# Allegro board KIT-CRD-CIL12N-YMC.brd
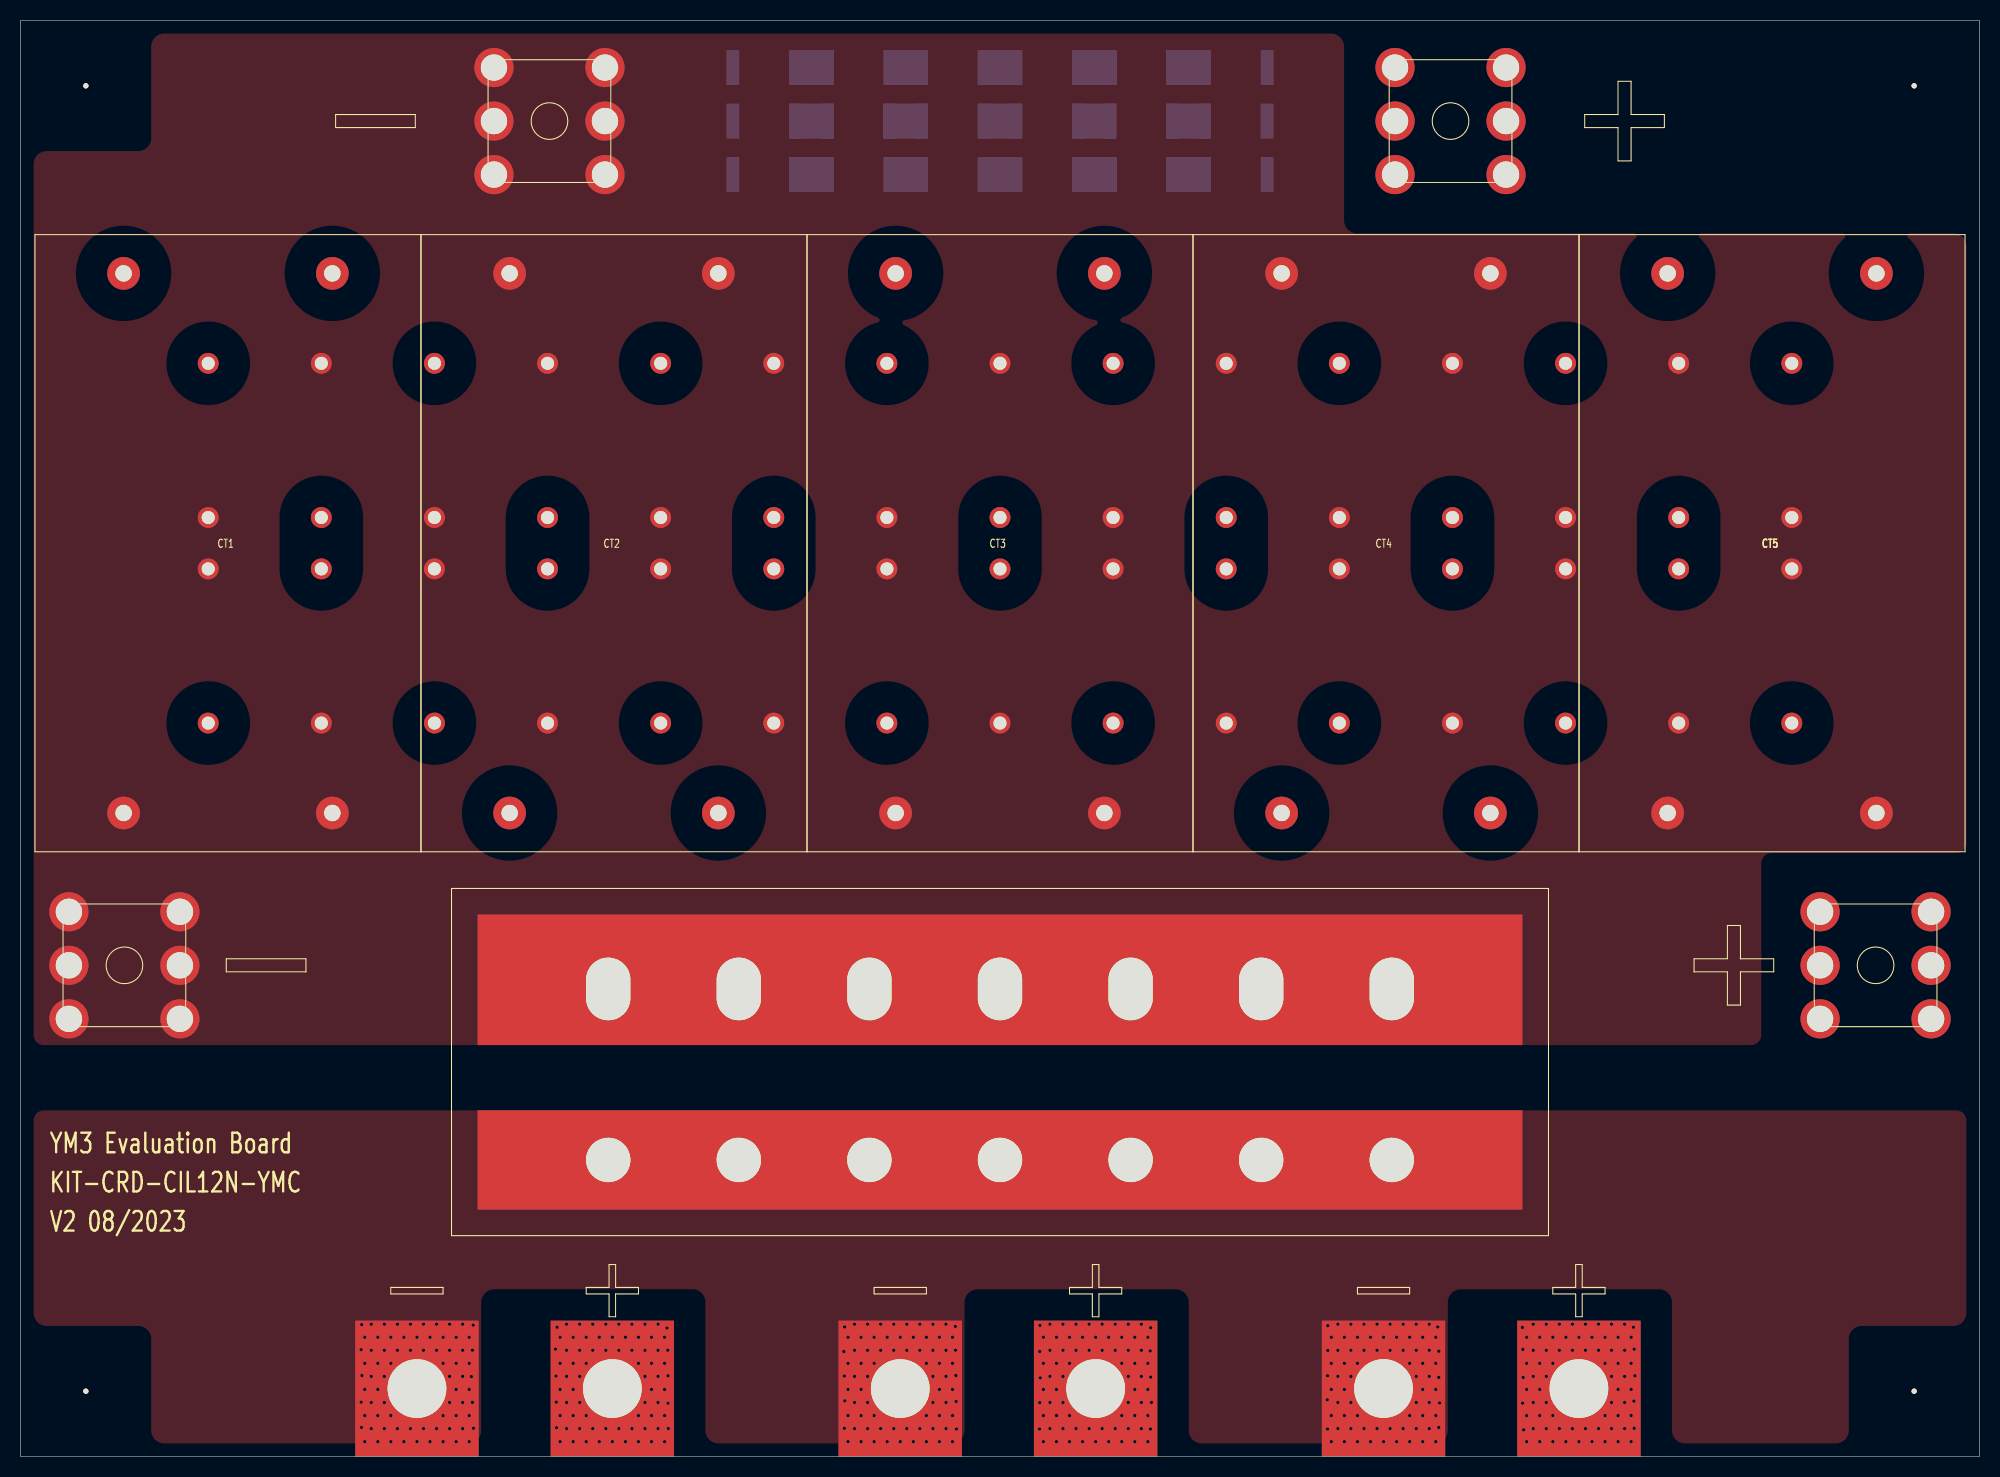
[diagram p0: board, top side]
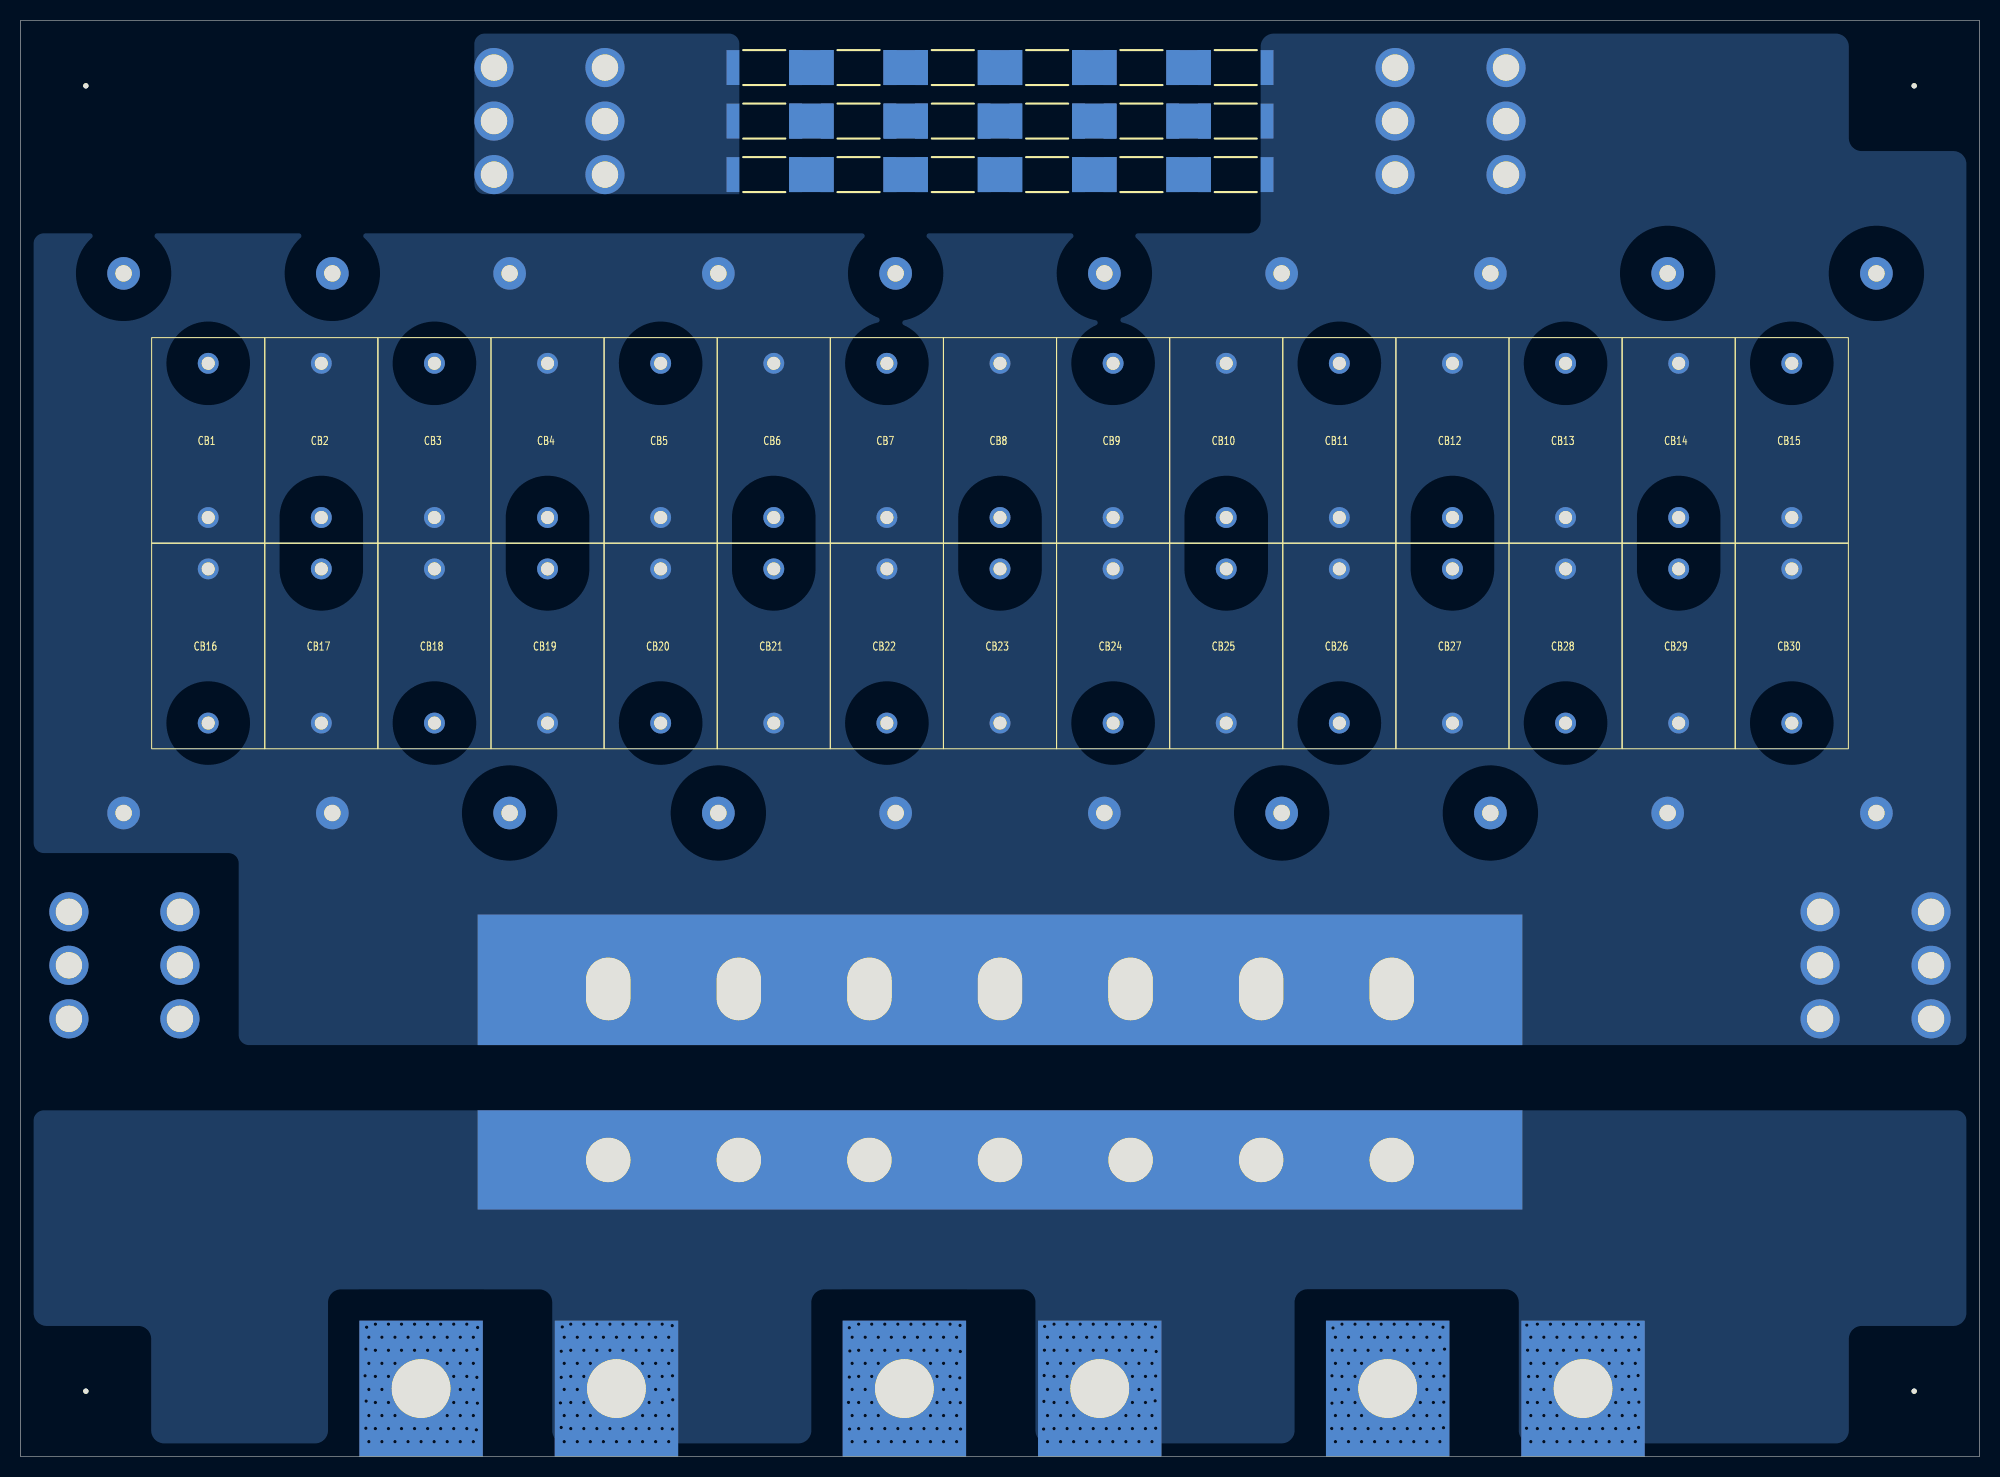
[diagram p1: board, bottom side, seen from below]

Outline 190.5 x 139.7 mm; copper layers: TOP, LAYER2, LAYER3, BOTTOM. Coordinates in mm from the lower left corner of the outline.
Outline path: 0,139.7 0,0 190.5,0 190.5,139.7 0,139.7

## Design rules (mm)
constraint set DEFAULT: min track width 0.178
net group BLEEDER 2/7 V+: nets N5310720 N5311468 N5311708
net group BLEEDER 3/7 V+: nets N5310714 N5311464 N5311704
net group BLEEDER 4/7 V+: nets N05002 N5311460 N5311700
net group BLEEDER 5/7 V+: nets N04998 N5311456 N5311696
net group BLEEDER 6/7 V+: nets N04994 N5311452 N5311692

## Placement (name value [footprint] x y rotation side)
CB1  0.1uF  [B32672L]  172.25 98.85 180 bottom
CB2  0.1uF  [B32672L]  161.25 98.85 0 bottom
CB3  0.1uF  [B32672L]  150.25 98.85 180 bottom
CB4  0.1uF  [B32672L]  139.25 98.85 0 bottom
CB5  0.1uF  [B32672L]  128.25 98.85 180 bottom
CB6  0.1uF  [B32672L]  117.25 98.85 0 bottom
CB7  0.1uF  [B32672L]  106.25 98.85 180 bottom
CB8  0.1uF  [B32672L]  95.25 98.85 0 bottom
CB9  0.1uF  [B32672L]  84.25 98.85 180 bottom
CB10  0.1uF  [B32672L]  73.25 98.85 0 bottom
CB11  0.1uF  [B32672L]  62.25 98.85 180 bottom
CB12  0.1uF  [B32672L]  51.25 98.85 0 bottom
CB13  0.1uF  [B32672L]  40.25 98.85 180 bottom
CB14  0.1uF  [B32672L]  29.25 98.85 0 bottom
CB15  0.1uF  [B32672L]  18.25 98.85 180 bottom
CB16  0.1uF  [B32672L]  172.25 78.85 0 bottom
CB17  0.1uF  [B32672L]  161.25 78.85 180 bottom
CB18  0.1uF  [B32672L]  150.25 78.85 0 bottom
CB19  0.1uF  [B32672L]  139.25 78.85 180 bottom
CB20  0.1uF  [B32672L]  128.25 78.85 0 bottom
CB21  0.1uF  [B32672L]  117.25 78.85 180 bottom
CB22  0.1uF  [B32672L]  106.25 78.85 0 bottom
CB23  0.1uF  [B32672L]  95.25 78.85 180 bottom
CB24  0.1uF  [B32672L]  84.25 78.85 0 bottom
CB25  0.1uF  [B32672L]  73.25 78.85 180 bottom
CB26  0.1uF  [B32672L]  62.25 78.85 0 bottom
CB27  0.1uF  [B32672L]  51.25 78.85 180 bottom
CB28  0.1uF  [B32672L]  40.25 78.85 0 bottom
CB29  0.1uF  [B32672L]  29.25 78.85 180 bottom
CB30  0.1uF  [B32672L]  18.25 78.85 0 bottom
CT1  40uF  [B32778G]  20.17 88.85 0 top
CT2  40uF  [B32778G]  57.71 88.85 180 top
CT3  40uF  [B32778G]  95.25 88.85 0 top
CT4  40uF  [B32778G]  132.79 88.85 180 top
CT5  40uF  [B32778G]  170.33 88.85 0 top
JT1  -  [8196]  51.44 129.92 270 top
JT2  -  [8196]  10.1 47.78 270 top
JT3  -  [8196]  139.06 129.92 270 top
JT4  -  [8196]  180.4 47.78 270 top
NOREF  -  [unnamed]  6.35 6.35 90 top
NOREF#2  -  [unnamed]  6.35 133.35 0 top
NOREF#3  -  [unnamed]  184.15 133.35 270 top
NOREF#4  -  [unnamed]  184.15 6.35 180 top
NOREF#5  -  [#2]  0 136.52 0 top
NOREF#6  -  [#2]  14.33 0 90 top
RB1  150k  [RESC6432X70N]  118.18 135.13 180 bottom
RB2  150k  [RESC6432X70N]  109.01 135.13 180 bottom
RB3  150k  [RESC6432X70N]  99.84 135.13 180 bottom
RB4  150k  [RESC6432X70N]  90.67 135.13 180 bottom
RB5  150k  [RESC6432X70N]  81.5 135.13 180 bottom
RB6  150k  [RESC6432X70N]  72.32 135.13 180 bottom
RB7  150k  [RESC6432X70N]  118.17 129.92 180 bottom
RB8  150k  [RESC6432X70N]  109 129.92 180 bottom
RB9  150k  [RESC6432X70N]  99.83 129.92 180 bottom
RB10  150k  [RESC6432X70N]  90.66 129.92 180 bottom
RB11  150k  [RESC6432X70N]  81.49 129.92 180 bottom
RB12  150k  [RESC6432X70N]  72.32 129.92 180 bottom
RB13  150k  [RESC6432X70N]  118.18 124.71 180 bottom
RB14  150k  [RESC6432X70N]  109.01 124.71 180 bottom
RB15  150k  [RESC6432X70N]  99.84 124.71 180 bottom
RB16  150k  [RESC6432X70N]  90.67 124.71 180 bottom
RB17  150k  [RESC6432X70N]  81.5 124.71 180 bottom
RB18  150k  [RESC6432X70N]  72.32 124.71 180 bottom
RT1  W-2-0025-4FC  [TM_CVR_W_14PIN_SLOTS]  95.25 38.37 0 top
U1  HybridPack_PowerOnly  [HYBRIDPACK_POWERONLY]  44.25 -10.03 0 top

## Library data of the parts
CB1-CB30 = CAP
CT1-CT5 = buscap
JT1-JT4 = Conn Plug 6
RB1-RB18 = R
RT1 = W-2-0025-4FC
U1 = HybridPack_PowerOnly

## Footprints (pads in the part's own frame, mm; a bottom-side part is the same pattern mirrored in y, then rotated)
8196
  round 3.81 hole 2.565: 1(-5.207,-5.397) 2(0,-5.397) 3(5.207,-5.397) 4(5.207,5.397) 5(0,5.397) 6(-5.207,5.397)
B32672L
  round 2.032 hole 1.27: 1(0,7.5) 2(0,-7.5)
B32778G
  round 3.175 hole 1.6: 1(-10.15,26.25) 2(10.15,26.25) 3(-10.15,-26.25) 4(10.15,-26.25)
HYBRIDPACK_POWERONLY
  rect 12x13.208 hole 5.715: N1(-5.7,16.631) N2(41.3,16.631) N3(88.3,16.631) P1(13.3,16.631) P2(60.3,16.631) P3(107.3,16.631)
RESC6432X70N
  rect 1.25x3.4 smd: 1(-3.05,0) 2(3.05,0)
TM_CVR_W_14PIN_SLOTS
  round 7.62 hole 4.318: 1(-38.1,-9.525) 2(-25.4,-9.525) 3(-12.7,-9.525) 4(0,-9.525) 5(12.7,-9.525) 6(25.4,-9.525) 7(38.1,-9.525)
  oval 7.62x9.398 hole 4.318x6.096: 8(38.1,7.112) 9(25.4,7.112) 10(12.7,7.112) 11(0,7.112) 12(-12.7,7.112) 13(-25.4,7.112) 14(-38.1,7.112)
unnamed
  round 0.508 hole 4.445 unplated: (0,0)

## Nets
+VIN: CB1.1 CB2.1 CB3.1 CB4.1 CB5.1 CB6.1 CB7.1 CB8.1 CB9.1 CB10.1 CB11.1 CB12.1 CB13.1 CB14.1 CB15.1 CB16.1 CB17.1 CB18.1 CB19.1 CB20.1 CB21.1 CB22.1 CB23.1 CB24.1 CB25.1 CB26.1 CB27.1 CB28.1 CB29.1 CB30.1 CT1.1 CT1.2 CT2.1 CT2.2 CT3.1 CT3.2 CT4.1 CT4.2 CT5.1 CT5.2 JT3.1 JT3.2 JT3.3 JT3.4 JT3.5 JT3.6 JT4.1 JT4.2 JT4.3 JT4.4 JT4.5 JT4.6 RB1.1 RB7.1 RB13.1 U1.P1 U1.P2 U1.P3
-VIN: CB1.2 CB2.2 CB3.2 CB4.2 CB5.2 CB6.2 CB7.2 CB8.2 CB9.2 CB10.2 CB11.2 CB12.2 CB13.2 CB14.2 CB15.2 CB16.2 CB17.2 CB18.2 CB19.2 CB20.2 CB21.2 CB22.2 CB23.2 CB24.2 CB25.2 CB26.2 CB27.2 CB28.2 CB29.2 CB30.2 CT1.3 CT1.4 CT2.3 CT2.4 CT3.3 CT3.4 CT4.3 CT4.4 CT5.3 CT5.4 JT1.1 JT1.2 JT1.3 JT1.4 JT1.5 JT1.6 JT2.1 JT2.2 JT2.3 JT2.4 JT2.5 JT2.6 RB6.2 RB12.2 RB18.2 RT1.8 RT1.9 RT1.10 RT1.11 RT1.12 RT1.13 RT1.14
SOURCE: RT1.1 RT1.2 RT1.3 RT1.4 RT1.5 RT1.6 RT1.7 U1.N1 U1.N2 U1.N3
N04994: RB1.2 RB2.1
N04998: RB2.2 RB3.1
N05002: RB3.2 RB4.1
N5310714: RB4.2 RB5.1
N5310720: RB5.2 RB6.1
N5311452: RB7.2 RB8.1
N5311456: RB8.2 RB9.1
N5311460: RB9.2 RB10.1
N5311464: RB10.2 RB11.1
N5311468: RB11.2 RB12.1
N5311692: RB13.2 RB14.1
N5311696: RB14.2 RB15.1
N5311700: RB15.2 RB16.1
N5311704: RB16.2 RB17.1
N5311708: RB17.2 RB18.1

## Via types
v1: diameter 0.61, hole 0.33, TOP to BOTTOM, 456 vias

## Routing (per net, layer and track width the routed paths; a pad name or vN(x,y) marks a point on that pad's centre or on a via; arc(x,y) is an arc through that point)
+VIN:
  vias: v1(52.02,10.44) v1(52.07,7.82) v1(52.1,5.28) v1(52.17,12.57) v1(52.12,2.79) v1(52.47,11.6) v1(52.47,9.06) v1(52.47,6.52) v1(52.47,3.98) v1(52.47,1.44) v1(53.1,12.87) v1(53.1,10.33) v1(53.1,7.79) v1(53.1,5.25) v1(53.1,2.71) v1(53.74,11.6) v1(53.74,9.06) v1(53.74,6.52) v1(53.74,3.98) v1(53.74,1.44) v1(54.37,12.87) v1(54.37,10.33) v1(54.37,7.79) v1(54.37,5.25) v1(54.37,2.71) v1(55.01,11.6) v1(55.01,9.06) v1(55.01,3.98) v1(55.01,1.44) v1(55.64,12.87) v1(55.64,10.33) v1(55.64,2.71) v1(56.28,11.6) v1(56.28,1.44) v1(56.91,12.87) v1(56.91,10.33) v1(56.91,2.71) v1(57.55,11.6) v1(57.55,1.44) v1(58.18,12.87) v1(58.18,10.33) v1(58.18,2.71) v1(58.82,11.6) v1(58.82,1.44) v1(59.45,12.87) v1(59.45,10.33) v1(59.45,2.71) v1(60.09,11.6) v1(60.09,9.06) v1(60.09,3.98) v1(60.09,1.44) v1(60.72,12.87) v1(60.72,10.33) v1(60.72,7.79) v1(60.72,5.25) v1(60.72,2.71) v1(61.36,11.6) v1(61.36,9.06) v1(61.36,6.52) v1(61.36,3.98) v1(61.36,1.44) v1(61.99,12.87) v1(61.99,10.33) v1(61.99,7.79) v1(61.99,5.25) v1(61.99,2.71) v1(62.63,11.6) v1(62.63,9.06) v1(62.63,6.52) v1(62.63,3.98) v1(62.63,1.44) v1(62.87,12.5) v1(62.94,10.34) v1(62.97,7.85) v1(62.97,5.18) v1(62.99,2.72) v1(99.09,2.67) v1(99.14,12.75) v1(99.11,10.21) v1(99.16,7.64) v1(99.11,5.23) v1(99.47,11.6) v1(99.47,9.06) v1(99.47,6.52) v1(99.47,3.98) v1(99.47,1.44) v1(100.1,12.87) v1(100.1,10.33) v1(100.1,7.79) v1(100.1,5.25) v1(100.1,2.71) v1(100.74,11.6) v1(100.74,9.06) v1(100.74,6.52) v1(100.74,3.98) v1(100.74,1.44) v1(101.37,12.87) v1(101.37,10.33) v1(101.37,7.79) v1(101.37,5.25) v1(101.37,2.71) v1(102.01,11.6) v1(102.01,9.06) v1(102.01,3.98) v1(102.01,1.44) v1(102.64,12.87) v1(102.64,10.33) v1(102.64,2.71) v1(103.28,11.6) v1(103.28,1.44) v1(103.91,12.87) v1(103.91,10.33) v1(103.91,2.71) v1(104.55,11.6) v1(104.55,1.44) v1(105.18,12.87) v1(105.18,10.33) v1(105.18,2.71) v1(105.82,11.6) v1(105.82,1.44) v1(106.45,12.87) v1(106.45,10.33) v1(106.45,2.71) v1(107.09,11.6) v1(107.09,9.06) v1(107.09,3.98) v1(107.09,1.44) v1(107.72,12.87) v1(107.72,10.33) v1(107.72,7.79) v1(107.72,5.25) v1(107.72,2.71) v1(108.36,11.6) v1(108.36,9.06) v1(108.36,6.52) v1(108.36,3.98) v1(108.36,1.44) v1(108.99,12.87) v1(108.99,10.33) v1(108.99,7.79) v1(108.99,5.25) v1(108.99,2.71) v1(109.63,11.6) v1(109.63,9.06) v1(109.63,6.52) v1(109.63,3.98) v1(109.63,1.44) v1(109.86,10.26) v1(109.88,2.67) v1(109.91,12.52) v1(109.91,7.72) v1(109.98,5.26) v1(146.05,12.55) v1(146.08,5.18) v1(146.1,10.41) v1(146.13,7.69) v1(146.18,2.59) v1(146.47,11.6) v1(146.47,9.06) v1(146.47,6.52) v1(146.47,3.98) v1(146.47,1.44) v1(147.1,12.87) v1(147.1,10.33) v1(147.1,7.79) v1(147.1,5.25) v1(147.1,2.71) v1(147.74,11.6) v1(147.74,9.06) v1(147.74,6.52) v1(147.74,3.98) v1(147.74,1.44) v1(148.37,12.87) v1(148.37,10.33) v1(148.37,7.79) v1(148.37,5.25) v1(148.37,2.71) v1(149.01,11.6) v1(149.01,9.06) v1(149.01,3.98) v1(149.01,1.44) v1(149.64,12.87) v1(149.64,10.33) v1(149.64,2.71) v1(150.28,11.6) v1(150.28,1.44) v1(150.91,12.87) v1(150.91,10.33) v1(150.91,2.71) v1(151.55,11.6) v1(151.55,1.44) v1(152.18,12.87) v1(152.18,10.33) v1(152.18,2.71) v1(152.82,11.6) v1(152.82,1.44) v1(153.45,12.87) v1(153.45,10.33) v1(153.45,2.71) v1(154.09,11.6) v1(154.09,9.06) v1(154.09,3.98) v1(154.09,1.44) v1(154.72,12.87) v1(154.72,10.33) v1(154.72,7.79) v1(154.72,5.25) v1(154.72,2.71) v1(155.36,11.6) v1(155.36,9.06) v1(155.36,6.52) v1(155.36,3.98) v1(155.36,1.44) v1(155.99,12.87) v1(155.99,10.33) v1(155.99,7.79) v1(155.99,5.25) v1(155.99,2.71) v1(156.63,11.6) v1(156.63,9.06) v1(156.63,6.52) v1(156.63,3.98) v1(156.63,1.44) v1(156.84,12.57) v1(156.9,5.38) v1(156.92,10.44) v1(157,7.85) v1(156.92,2.74)
SOURCE:
  vias: v1(33.17,12.83) v1(33.12,10.39) v1(33.2,7.87) v1(33.12,5.28) v1(33.15,2.82) v1(33.47,11.6) v1(33.47,9.06) v1(33.47,6.52) v1(33.47,3.98) v1(33.47,1.44) v1(34.1,12.87) v1(34.1,10.33) v1(34.1,7.79) v1(34.1,5.25) v1(34.1,2.71) v1(34.74,11.6) v1(34.74,9.06) v1(34.74,6.52) v1(34.74,3.98) v1(34.74,1.44) v1(35.37,12.87) v1(35.37,10.33) v1(35.37,7.79) v1(35.37,5.25) v1(35.37,2.71) v1(36.01,11.6) v1(36.01,9.06) v1(36.01,3.98) v1(36.01,1.44) v1(36.64,12.87) v1(36.64,10.33) v1(36.64,2.71) v1(37.28,11.6) v1(37.28,1.44) v1(37.91,12.87) v1(37.91,10.33) v1(37.91,2.71) v1(38.55,11.6) v1(38.55,1.44) v1(39.18,12.87) v1(39.18,10.33) v1(39.18,2.71) v1(39.82,11.6) v1(39.82,1.44) v1(40.45,12.87) v1(40.45,10.33) v1(40.45,2.71) v1(41.09,11.6) v1(41.09,9.06) v1(41.09,3.98) v1(41.09,1.44) v1(41.72,12.87) v1(41.72,10.33) v1(41.72,7.79) v1(41.72,5.25) v1(41.72,2.71) v1(42.36,11.6) v1(42.36,9.06) v1(42.36,6.52) v1(42.36,3.98) v1(42.36,1.44) v1(42.99,12.87) v1(42.99,10.33) v1(42.99,7.79) v1(42.99,5.25) v1(42.99,2.71) v1(43.63,11.6) v1(43.63,9.06) v1(43.63,6.52) v1(43.63,3.98) v1(43.63,1.44) v1(43.84,7.77) v1(43.94,10.34) v1(43.94,5.26) v1(44.02,12.77) v1(44.04,2.74) v1(80.06,10.21) v1(80.14,12.6) v1(80.11,7.82) v1(80.16,5.41) v1(80.11,2.74) v1(80.47,11.6) v1(80.47,9.06) v1(80.47,6.52) v1(80.47,3.98) v1(80.47,1.44) v1(81.1,12.87) v1(81.1,10.33) v1(81.1,7.79) v1(81.1,5.25) v1(81.1,2.71) v1(81.74,11.6) v1(81.74,9.06) v1(81.74,6.52) v1(81.74,3.98) v1(81.74,1.44) v1(82.37,12.87) v1(82.37,10.33) v1(82.37,7.79) v1(82.37,5.25) v1(82.37,2.71) v1(83.01,11.6) v1(83.01,9.06) v1(83.01,3.98) v1(83.01,1.44) v1(83.64,12.87) v1(83.64,10.33) v1(83.64,2.71) v1(84.28,11.6) v1(84.28,1.44) v1(84.91,12.87) v1(84.91,10.33) v1(84.91,2.71) v1(85.55,11.6) v1(85.55,1.44) v1(86.18,12.87) v1(86.18,10.33) v1(86.18,2.71) v1(86.82,11.6) v1(86.82,1.44) v1(87.45,12.87) v1(87.45,10.33) v1(87.45,2.71) v1(88.09,11.6) v1(88.09,9.06) v1(88.09,3.98) v1(88.09,1.44) v1(88.72,12.87) v1(88.72,10.33) v1(88.72,7.79) v1(88.72,5.25) v1(88.72,2.71) v1(89.36,11.6) v1(89.36,9.06) v1(89.36,6.52) v1(89.36,3.98) v1(89.36,1.44) v1(89.99,12.87) v1(89.99,10.33) v1(89.99,7.79) v1(89.99,5.25) v1(89.99,2.71) v1(90.63,11.6) v1(90.63,9.06) v1(90.63,6.52) v1(90.63,3.98) v1(90.63,1.44) v1(90.91,12.65) v1(90.93,10.34) v1(90.96,7.87) v1(90.98,5.36) v1(91.01,2.67) v1(127.08,5.51) v1(127.13,12.72) v1(127.13,10.31) v1(127.1,7.85) v1(127.1,2.67) v1(127.47,11.6) v1(127.47,9.06) v1(127.47,6.52) v1(127.47,3.98) v1(127.47,1.44) v1(128.1,12.87) v1(128.1,10.33) v1(128.1,7.79) v1(128.1,5.25) v1(128.1,2.71) v1(128.74,11.6) v1(128.74,9.06) v1(128.74,6.52) v1(128.74,3.98) v1(128.74,1.44) v1(129.37,12.87) v1(129.37,10.33) v1(129.37,7.79) v1(129.37,5.25) v1(129.37,2.71) v1(130.01,11.6) v1(130.01,9.06) v1(130.01,3.98) v1(130.01,1.44) v1(130.64,12.87) v1(130.64,10.33) v1(130.64,2.71) v1(131.28,11.6) v1(131.28,1.44) v1(131.91,12.87) v1(131.91,10.33) v1(131.91,2.71) v1(132.55,11.6) v1(132.55,1.44) v1(133.18,12.87) v1(133.18,10.33) v1(133.18,2.71) v1(133.82,11.6) v1(133.82,1.44) v1(134.45,12.87) v1(134.45,10.33) v1(134.45,2.71) v1(135.09,11.6) v1(135.09,9.06) v1(135.09,3.98) v1(135.09,1.44) v1(135.72,12.87) v1(135.72,10.33) v1(135.72,7.79) v1(135.72,5.25) v1(135.72,2.71) v1(136.36,11.6) v1(136.36,9.06) v1(136.36,6.52) v1(136.36,3.98) v1(136.36,1.44) v1(136.99,12.87) v1(136.99,10.33) v1(136.99,7.79) v1(136.99,5.25) v1(136.99,2.71) v1(137.63,11.6) v1(137.63,9.06) v1(137.63,6.52) v1(137.63,3.98) v1(137.63,1.44) v1(137.82,12.6) v1(137.92,10.23) v1(137.92,7.69) v1(138,5.21) v1(137.92,2.82)

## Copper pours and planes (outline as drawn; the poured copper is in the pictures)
-VIN on TOP (solid shape): 146.05,40.02 44.45,40.02 44.45,52.72 146.05,52.72
-VIN on BOTTOM (solid shape): 146.05,40.02 44.45,40.02 44.45,52.72 146.05,52.72
-VIN on TOP: 1.27,41.02 1.56,40.32 2.27,40.02 168.29,40.02 169,40.32 169.29,41.02 169.29,57.7 169.58,58.41 170.29,58.7 188.23,58.7 188.94,59 189.23,59.7 189.23,117.73 188.86,118.63 187.96,119 129.98,119 129.09,119.37 128.71,120.27 128.71,137.16 128.34,138.06 127.44,138.43 13.97,138.43 13.07,138.06 12.7,137.16 12.7,128.27 12.33,127.37 11.43,127 2.54,127 1.64,126.63 1.27,125.73
-VIN on BOTTOM: 1.27,41.02 1.56,40.32 2.27,40.02 168.29,40.02 169,40.32 169.29,41.02 169.29,57.7 169.58,58.41 170.29,58.7 188.23,58.7 188.94,59 189.23,59.7 189.23,118 188.94,118.7 188.23,119 71.17,119 70.27,119.37 69.9,120.27 69.9,137.16 69.53,138.06 68.63,138.43 13.97,138.43 13.07,138.06 12.7,137.16 12.7,128.27 12.33,127.37 11.43,127 2.54,127 1.64,126.63 1.27,125.73
(no net) on BOTTOM: 102.26,126.41 102.26,123.01 106.58,123.01 106.58,126.41
(no net) on BOTTOM: 93.09,126.41 93.09,123.01 97.41,123.01 97.41,126.41
(no net) on BOTTOM: 83.92,131.62 83.92,128.22 88.24,128.22 88.24,131.62
(no net) on BOTTOM: 74.75,136.83 74.75,133.43 79.07,133.43 79.07,136.83
(no net) on BOTTOM: 102.26,136.83 102.26,133.43 106.58,133.43 106.58,136.83
(no net) on BOTTOM: 111.43,131.62 111.43,128.22 115.75,128.22 115.75,131.62
(no net) on BOTTOM: 74.75,126.41 74.75,123.01 79.07,123.01 79.07,126.41
(no net) on BOTTOM: 93.09,136.83 93.09,133.43 97.41,133.43 97.41,136.83
(no net) on BOTTOM: 83.92,136.83 83.92,133.43 88.24,133.43 88.24,136.83
(no net) on BOTTOM: 111.43,126.41 111.43,123.01 115.75,123.01 115.75,126.41
(no net) on BOTTOM: 102.26,131.62 102.26,128.22 106.58,128.22 106.58,131.62
(no net) on BOTTOM: 111.43,136.83 111.43,133.43 115.75,133.43 115.75,136.83
(no net) on BOTTOM: 74.75,131.62 74.75,128.22 79.07,128.22 79.07,131.62
(no net) on BOTTOM: 93.09,131.62 93.09,128.22 97.41,128.22 97.41,131.62
(no net) on BOTTOM: 83.92,126.41 83.92,123.01 88.24,123.01 88.24,126.41
SOURCE on TOP (solid shape): 146.05,24.02 44.45,24.02 44.45,33.67 146.05,33.67
SOURCE on BOTTOM (solid shape): 146.05,24.02 44.45,24.02 44.45,33.67 146.05,33.67
SOURCE on TOP: 1.27,32.67 1.56,33.38 2.27,33.67 188.23,33.67 188.94,33.38 189.23,32.67 189.23,13.97 188.86,13.07 187.96,12.7 179.07,12.7 178.17,12.33 177.8,11.43 177.8,2.54 177.43,1.64 176.53,1.27 161.87,1.27 160.97,1.64 160.6,2.54 160.6,14.99 160.23,15.89 159.33,16.26 140.07,16.26 140.07,16.25 139.17,15.88 138.8,14.98 138.8,2.54 138.43,1.64 137.53,1.27 114.87,1.27 113.97,1.64 113.6,2.54 113.6,14.99 113.23,15.89 112.33,16.26 93.07,16.26 93.07,16.25 92.17,15.88 91.8,14.98 91.8,2.54 91.43,1.64 90.53,1.27 67.87,1.27 66.97,1.64 66.6,2.54 66.6,15 66.23,15.9 65.33,16.27 46.07,16.27 46.07,16.25 45.17,15.88 44.8,14.98 44.8,2.54 44.43,1.64 43.53,1.27 13.97,1.27 13.07,1.64 12.7,2.54 12.7,11.43 12.33,12.33 11.43,12.7 2.54,12.7 1.64,13.07 1.27,13.97
N04994 on BOTTOM (solid shape): 115.75,133.43 111.43,133.43 111.43,136.83 115.75,136.83
N04998 on BOTTOM (solid shape): 106.58,133.43 102.26,133.43 102.26,136.83 106.58,136.83
N05002 on BOTTOM (solid shape): 97.41,133.43 93.09,133.43 93.09,136.83 97.41,136.83
N5310714 on BOTTOM (solid shape): 88.24,133.43 83.92,133.43 83.92,136.83 88.24,136.83
N5310720 on BOTTOM (solid shape): 79.07,133.43 74.75,133.43 74.75,136.83 79.07,136.83
N5311452 on BOTTOM (solid shape): 115.75,128.22 111.43,128.22 111.43,131.62 115.75,131.62
N5311456 on BOTTOM (solid shape): 106.58,128.22 102.26,128.22 102.26,131.62 106.58,131.62
N5311460 on BOTTOM (solid shape): 97.41,128.22 93.09,128.22 93.09,131.62 97.41,131.62
N5311464 on BOTTOM (solid shape): 88.24,128.22 83.92,128.22 83.92,131.62 88.24,131.62
N5311468 on BOTTOM (solid shape): 79.07,128.22 74.75,128.22 74.75,131.62 79.07,131.62
N5311692 on BOTTOM (solid shape): 115.75,123.01 111.43,123.01 111.43,126.41 115.75,126.41
N5311696 on BOTTOM (solid shape): 106.58,123.01 102.26,123.01 102.26,126.41 106.58,126.41
N5311700 on BOTTOM (solid shape): 97.41,123.01 93.09,123.01 93.09,126.41 97.41,126.41
N5311704 on BOTTOM (solid shape): 88.24,123.01 83.92,123.01 83.92,126.41 88.24,126.41
N5311708 on BOTTOM (solid shape): 79.07,123.01 74.75,123.01 74.75,126.41 79.07,126.41

Small or netless copper shapes (teardrops, artwork), in the pictures only: 2 on BOTTOM, 1 on LAYER2, 1 on LAYER3

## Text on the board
Ref Des/Silkscreen Top: YM3 Evaluation Board | KIT-CRD-CIL12N-YMC | V2 08/2023
DISPLAY_BOTTOM: FIGURE | FINISHED_SIZE | 13.0 | 50.0 | 63.0 | 101.0 | 170.0 | 225.0 | 175.0 | DRILL CHART: TOP to BOTTOM | ALL UNITS ARE IN MILS | ROTATION | - | PLATED | NON-PLATED | QTY | 456 | 60 | 20 | 24 | 7 | 6 | 4 | 577 | TOTAL HOLES:
DEVICE_TYPE_BOTTOM: FIGURE | FINISHED_SIZE | 240.0x170.0 | SLOT HOLES: TOP to BOTTOM | ALL UNITS ARE IN MILS | ROTATION | 90.000 | PLATED | QTY | 7 | TOTAL HOLES:
